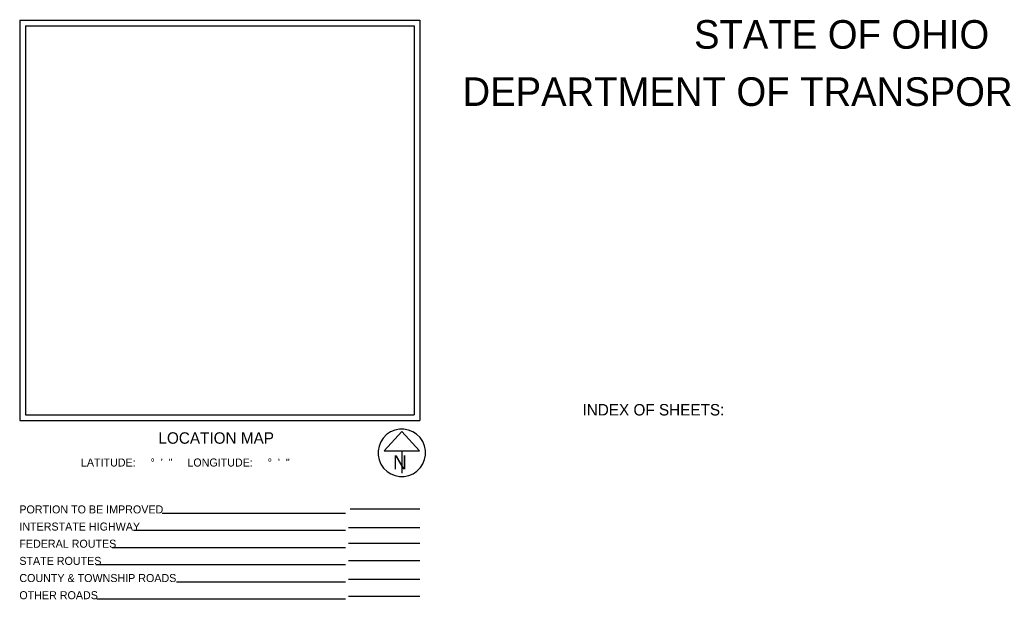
# Model space of a CAD drawing. Extents: x -4 to 116, y -17 to 29.
# Drawn here: x 86.48 to 103.7, y 18.88 to 29.02 of the extents above; entities that cross this region are included whole.
import ezdxf

# ---------------------------------------------------------------- set-up
doc = ezdxf.new("R2010")
doc.units = 0
doc.layers.add('SH_Data', color=7, linetype='Continuous')
doc.layers.add('SH_Text', color=7, linetype='Continuous')

msp = doc.modelspace()

# ---------------------------------------------------------------- linework, layer by layer
at = {"layer": 'SH_Data'}
for p, q in [((86.48, 29.008), (93.48, 29.008)), ((86.48, 29.008), (86.48, 22.008)), ((93.48, 29.008), (93.48, 22.008)), ((86.58, 28.908), (86.58, 22.108)), ((86.58, 28.908), (93.38, 28.908)), ((93.38, 28.908), (93.38, 22.108)), ((86.58, 22.108), (93.38, 22.108)), ((86.58, 22.108), (86.58, 22.108)), ((86.48, 22.008), (93.48, 22.008)), ((93.164, 21.817), (92.857, 21.476)), ((93.472, 21.476), (93.164, 21.817)), ((92.857, 21.476), (93.472, 21.476)), ((93.164, 21.476), (93.164, 21.089)), ((93.164, 21.443), (93.164, 21.443)), ((93.164, 21.443), (93.164, 21.443)), ((92.18, 20.384), (88.974, 20.384)), ((92.263, 20.463), (93.48, 20.463)), ((92.18, 20.084), (88.469, 20.084)), ((93.48, 20.129), (92.23, 20.129)), ((93.48, 19.857), (92.23, 19.857)), ((92.18, 19.784), (88.099, 19.784)), ((92.18, 19.484), (87.809, 19.484)), ((93.48, 19.557), (92.23, 19.557)), ((92.18, 19.184), (89.225, 19.184)), ((93.48, 19.23), (92.23, 19.23)), ((92.18, 18.884), (87.827, 18.884)), ((93.48, 18.93), (92.23, 18.93))]:
    msp.add_line(p, q, dxfattribs=at)
msp.add_arc((93.164, 21.443), 0.415, 129.7798, 129.7633, dxfattribs=at)

# ---------------------------------------------------------------- texts
msp.add_text('N', height=0.25, dxfattribs=at).set_placement((93.009, 21.152))
at = {"layer": 'SH_Text'}
for s, height, p in [('STATE OF OHIO', 0.5, (98.275, 28.508)), ('DEPARTMENT OF TRANSPORTATION', 0.5, (94.226, 27.508)), ('INDEX OF SHEETS:', 0.2, (96.324, 22.096)), ('LOCATION MAP', 0.2, (88.907, 21.602)), ('LATITUDE:     °  \'  "     LONGITUDE:     °  \'  "', 0.14, (87.551, 21.204)), ('PORTION TO BE IMPROVED', 0.14, (86.474, 20.384)), ('INTERSTATE HIGHWAY', 0.14, (86.474, 20.084)), ('FEDERAL ROUTES', 0.14, (86.474, 19.784)), ('STATE ROUTES', 0.14, (86.474, 19.484)), ('COUNTY & TOWNSHIP ROADS', 0.14, (86.474, 19.184)), ('OTHER ROADS', 0.14, (86.474, 18.884))]:
    msp.add_text(s, height=height, dxfattribs=at).set_placement(p)

doc.saveas('drawing.dxf')
